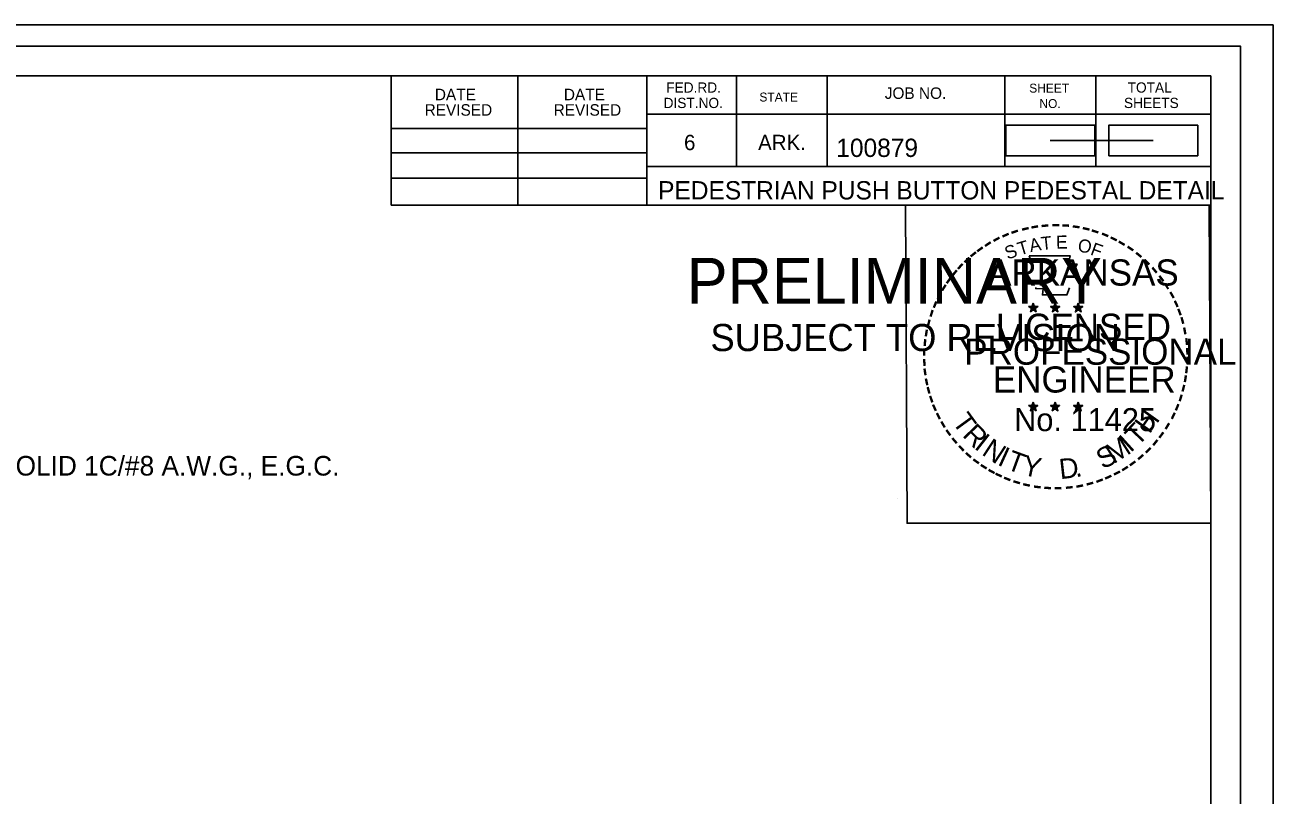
# Model space of a CAD drawing. Extents: x 1695551 to 1695718, y 544410 to 544516.
# Drawn here: x 1695670.25 to 1695717.93, y 544486.76 to 544516.2 of the extents above; entities that cross this region are included whole.
import ezdxf

# ---------------------------------------------------------------- set-up
doc = ezdxf.new("R2010")
doc.units = 0
for name, color, linetype in [('0_Plot Shape', 7, 'Continuous'), ('R_Border', 7, 'Continuous'), ('R_Border PE', 7, 'Continuous'), ('R_Border Prem', 7, 'Continuous'), ('R_Draft', 7, 'Continuous'), ('R_No Plot', 7, 'Continuous'), ('R_NoPlot', 7, 'Continuous'), ('R_Proposed Road', 7, 'Continuous')]:
    doc.layers.add(name, color=color, linetype=linetype)

msp = doc.modelspace()

# ---------------------------------------------------------------- linework, layer by layer
at = {"layer": '0_Plot Shape'}
msp.add_lwpolyline([(1695551.694, 544515.386), (1695716.694, 544515.386), (1695716.694, 544410.386), (1695551.694, 544410.386)], close=True, dxfattribs=at)
at = {"layer": 'R_Border'}
for p, q in [((1695557.469, 544514.251), (1695715.559, 544514.251)), ((1695684.239, 544509.311), (1695684.239, 544514.251)), ((1695689.079, 544509.311), (1695689.079, 544514.251)), ((1695694.009, 544514.251), (1695694.009, 544509.311)), ((1695697.429, 544514.251), (1695697.429, 544510.781)), ((1695700.899, 544514.251), (1695700.899, 544510.781)), ((1695707.689, 544514.251), (1695707.689, 544510.781)), ((1695711.159, 544514.251), (1695711.159, 544510.781)), ((1695715.559, 544411.521), (1695715.559, 544514.251)), ((1695715.559, 544512.781), (1695694.009, 544512.781)), ((1695715.559, 544512.791), (1695715.559, 544512.791)), ((1695684.239, 544512.241), (1695694.009, 544512.241)), ((1695684.239, 544511.311), (1695694.009, 544511.311)), ((1695715.559, 544510.781), (1695694.009, 544510.781)), ((1695695.489, 544510.781), (1695715.559, 544510.781)), ((1695684.239, 544510.341), (1695694.009, 544510.341)), ((1695715.559, 544509.311), (1695684.239, 544509.311))]:
    msp.add_line(p, q, dxfattribs=at)
msp.add_lwpolyline([(1695711.657, 544511.198), (1695715.06, 544511.198), (1695715.06, 544512.364), (1695711.657, 544512.364)], close=True, dxfattribs=at)
at = {"layer": 'R_Border PE'}
for p, q in [((1695708.601, 544505.438), (1695708.776, 544505.383)), ((1695708.601, 544505.438), (1695708.728, 544505.416)), ((1695708.601, 544505.438), (1695708.72, 544505.377)), ((1695708.668, 544505.234), (1695708.776, 544505.383)), ((1695708.668, 544505.234), (1695708.731, 544505.356)), ((1695708.668, 544505.234), (1695708.775, 544505.343)), ((1695708.776, 544505.565), (1695708.755, 544505.439)), ((1695708.882, 544505.234), (1695708.775, 544505.341)), ((1695708.776, 544505.383), (1695708.776, 544505.565)), ((1695708.776, 544505.565), (1695708.8, 544505.44)), ((1695708.949, 544505.438), (1695708.776, 544505.383)), ((1695708.882, 544505.234), (1695708.776, 544505.383)), ((1695708.949, 544505.438), (1695708.806, 544505.414)), ((1695708.882, 544505.234), (1695708.814, 544505.38)), ((1695708.949, 544505.438), (1695708.847, 544505.387)), ((1695709.436, 544505.438), (1695709.611, 544505.383)), ((1695709.436, 544505.438), (1695709.563, 544505.416)), ((1695709.436, 544505.438), (1695709.555, 544505.377)), ((1695709.503, 544505.234), (1695709.611, 544505.383)), ((1695709.503, 544505.234), (1695709.566, 544505.356)), ((1695709.503, 544505.234), (1695709.61, 544505.343)), ((1695709.611, 544505.565), (1695709.59, 544505.439)), ((1695709.717, 544505.234), (1695709.61, 544505.341)), ((1695709.611, 544505.383), (1695709.611, 544505.565)), ((1695709.611, 544505.565), (1695709.635, 544505.44)), ((1695709.784, 544505.438), (1695709.611, 544505.383)), ((1695709.717, 544505.234), (1695709.611, 544505.383)), ((1695709.784, 544505.438), (1695709.641, 544505.414)), ((1695709.717, 544505.234), (1695709.649, 544505.38)), ((1695709.784, 544505.438), (1695709.682, 544505.387)), ((1695710.318, 544505.432), (1695710.493, 544505.377)), ((1695710.318, 544505.432), (1695710.445, 544505.41)), ((1695710.318, 544505.432), (1695710.437, 544505.371)), ((1695710.385, 544505.228), (1695710.493, 544505.377)), ((1695710.385, 544505.228), (1695710.448, 544505.35)), ((1695710.385, 544505.228), (1695710.492, 544505.337)), ((1695710.493, 544505.559), (1695710.472, 544505.433)), ((1695710.599, 544505.228), (1695710.492, 544505.335)), ((1695710.493, 544505.377), (1695710.493, 544505.559)), ((1695710.493, 544505.559), (1695710.517, 544505.434)), ((1695710.666, 544505.432), (1695710.493, 544505.377)), ((1695710.599, 544505.228), (1695710.493, 544505.377)), ((1695710.666, 544505.432), (1695710.523, 544505.408)), ((1695710.599, 544505.228), (1695710.531, 544505.374)), ((1695710.666, 544505.432), (1695710.564, 544505.381)), ((1695708.599, 544501.652), (1695708.774, 544501.596)), ((1695708.599, 544501.652), (1695708.726, 544501.629)), ((1695708.599, 544501.652), (1695708.718, 544501.591)), ((1695708.666, 544501.448), (1695708.774, 544501.596)), ((1695708.666, 544501.448), (1695708.729, 544501.57)), ((1695708.666, 544501.448), (1695708.773, 544501.556)), ((1695708.774, 544501.779), (1695708.753, 544501.653)), ((1695708.88, 544501.448), (1695708.773, 544501.555)), ((1695708.774, 544501.596), (1695708.774, 544501.779)), ((1695708.774, 544501.779), (1695708.798, 544501.654)), ((1695708.947, 544501.652), (1695708.774, 544501.596)), ((1695708.88, 544501.448), (1695708.774, 544501.596)), ((1695708.947, 544501.652), (1695708.804, 544501.627)), ((1695708.88, 544501.448), (1695708.812, 544501.593)), ((1695708.947, 544501.652), (1695708.845, 544501.601)), ((1695709.434, 544501.652), (1695709.608, 544501.596)), ((1695709.434, 544501.652), (1695709.56, 544501.629)), ((1695709.434, 544501.652), (1695709.552, 544501.591)), ((1695709.5, 544501.448), (1695709.608, 544501.596)), ((1695709.5, 544501.448), (1695709.563, 544501.57)), ((1695709.5, 544501.448), (1695709.607, 544501.556)), ((1695709.608, 544501.779), (1695709.588, 544501.653)), ((1695709.715, 544501.448), (1695709.607, 544501.555)), ((1695709.608, 544501.596), (1695709.608, 544501.779)), ((1695709.608, 544501.779), (1695709.633, 544501.654)), ((1695709.782, 544501.652), (1695709.608, 544501.596)), ((1695709.715, 544501.448), (1695709.608, 544501.596)), ((1695709.782, 544501.652), (1695709.639, 544501.627)), ((1695709.715, 544501.448), (1695709.646, 544501.593)), ((1695709.782, 544501.652), (1695709.68, 544501.601)), ((1695710.317, 544501.647), (1695710.492, 544501.591)), ((1695710.317, 544501.647), (1695710.444, 544501.624)), ((1695710.317, 544501.647), (1695710.436, 544501.586)), ((1695710.384, 544501.443), (1695710.492, 544501.591)), ((1695710.384, 544501.443), (1695710.447, 544501.565)), ((1695710.384, 544501.443), (1695710.491, 544501.551)), ((1695710.492, 544501.774), (1695710.471, 544501.648)), ((1695710.598, 544501.443), (1695710.491, 544501.55)), ((1695710.492, 544501.591), (1695710.492, 544501.774)), ((1695710.492, 544501.774), (1695710.516, 544501.649)), ((1695710.665, 544501.647), (1695710.492, 544501.591)), ((1695710.598, 544501.443), (1695710.492, 544501.591)), ((1695710.665, 544501.647), (1695710.522, 544501.622)), ((1695710.598, 544501.443), (1695710.53, 544501.588)), ((1695710.665, 544501.647), (1695710.563, 544501.596))]:
    msp.add_line(p, q, dxfattribs=at)
for points in [[(1695708.622, 544507.377), (1695708.756, 544506.964)], [(1695710.377, 544506.916), (1695710.448, 544507.058), (1695710.106, 544507.046), (1695710.18, 544507.377), (1695708.622, 544507.377)], [(1695708.868, 544506.166), (1695708.868, 544506.122), (1695709.149, 544506.113), (1695709.122, 544505.876), (1695710.057, 544505.876), (1695710.158, 544506.144)], [(1695708.776, 544505.565), (1695708.882, 544505.234), (1695708.601, 544505.438), (1695708.949, 544505.438), (1695708.668, 544505.234), (1695708.776, 544505.565)], [(1695709.611, 544505.565), (1695709.717, 544505.234), (1695709.436, 544505.438), (1695709.784, 544505.438), (1695709.503, 544505.234), (1695709.611, 544505.565)], [(1695710.493, 544505.559), (1695710.599, 544505.228), (1695710.318, 544505.432), (1695710.666, 544505.432), (1695710.385, 544505.228), (1695710.493, 544505.559)], [(1695708.774, 544501.779), (1695708.88, 544501.448), (1695708.599, 544501.652), (1695708.947, 544501.652), (1695708.666, 544501.448), (1695708.774, 544501.779)], [(1695709.608, 544501.779), (1695709.715, 544501.448), (1695709.434, 544501.652), (1695709.782, 544501.652), (1695709.5, 544501.448), (1695709.608, 544501.779)], [(1695710.492, 544501.774), (1695710.598, 544501.443), (1695710.317, 544501.647), (1695710.665, 544501.647), (1695710.384, 544501.443), (1695710.492, 544501.774)]]:
    msp.add_lwpolyline(points, dxfattribs=at)
for centre, radius in [((1695708.775, 544505.383), 0.0861), ((1695708.775, 544505.383), 0.0723), ((1695708.775, 544505.383), 0.0579), ((1695708.775, 544505.383), 0.0495), ((1695708.775, 544505.383), 0.0374), ((1695708.775, 544505.383), 0.0248), ((1695708.775, 544505.383), 0.0148), ((1695709.61, 544505.383), 0.0861), ((1695709.61, 544505.383), 0.0723), ((1695709.61, 544505.383), 0.0579), ((1695709.61, 544505.383), 0.0495), ((1695709.61, 544505.383), 0.0374), ((1695709.61, 544505.383), 0.0248), ((1695709.61, 544505.383), 0.0148), ((1695710.492, 544505.377), 0.0861), ((1695710.492, 544505.377), 0.0723), ((1695710.492, 544505.377), 0.0579), ((1695710.492, 544505.377), 0.0495), ((1695710.492, 544505.377), 0.0374), ((1695710.492, 544505.377), 0.0248), ((1695710.492, 544505.377), 0.0148), ((1695708.773, 544501.596), 0.0861), ((1695708.773, 544501.596), 0.0723), ((1695708.773, 544501.596), 0.0579), ((1695708.773, 544501.596), 0.0495), ((1695708.773, 544501.596), 0.0374), ((1695708.773, 544501.596), 0.0248), ((1695708.773, 544501.596), 0.0148), ((1695709.608, 544501.596), 0.0861), ((1695709.608, 544501.596), 0.0723), ((1695709.608, 544501.596), 0.0579), ((1695709.608, 544501.596), 0.0495), ((1695709.608, 544501.596), 0.0374), ((1695709.608, 544501.596), 0.0248), ((1695709.608, 544501.596), 0.0148), ((1695710.491, 544501.591), 0.0861), ((1695710.491, 544501.591), 0.0723), ((1695710.491, 544501.591), 0.0579), ((1695710.491, 544501.591), 0.0495), ((1695710.491, 544501.591), 0.0374), ((1695710.491, 544501.591), 0.0248), ((1695710.491, 544501.591), 0.0148)]:
    msp.add_circle(centre, radius, dxfattribs=at)
at = {"layer": 'R_No Plot'}
for p, q in [((1695551.268, 544516.198), (1695717.935, 544516.198)), ((1695703.576, 544498.083), (1695703.576, 544498.083))]:
    msp.add_line(p, q, dxfattribs=at)
for points in [[(1695551.265, 544516.198), (1695717.935, 544516.198), (1695717.935, 544409.529), (1695551.265, 544409.529)], [(1695703.894, 544509.311), (1695715.498, 544509.311), (1695715.559, 544497.145), (1695703.955, 544497.145)]]:
    msp.add_lwpolyline(points, close=True, dxfattribs=at)
at = {"layer": 'R_NoPlot'}
msp.add_line((1695709.424, 544511.781), (1695713.359, 544511.781), dxfattribs=at)
at = {"layer": 'R_Proposed Road'}
msp.add_lwpolyline([(1695707.722, 544511.198), (1695711.125, 544511.198), (1695711.125, 544512.364), (1695707.722, 544512.364)], close=True, dxfattribs=at)

# ---------------------------------------------------------------- texts
at = {"layer": 'R_Border'}
for s, height, p in [('FED.RD.', 0.391, (1695694.749, 544513.611)), ('JOB NO.', 0.4396, (1695703.099, 544513.371)), ('SHEET', 0.342, (1695708.619, 544513.611)), ('TOTAL', 0.391, (1695712.379, 544513.611)), ('DATE', 0.4396, (1695685.908, 544513.319)), ('DATE', 0.4396, (1695690.838, 544513.319)), ('DIST.NO.', 0.391, (1695694.649, 544513.021)), ('STATE', 0.342, (1695698.309, 544513.271)), ('NO.', 0.342, (1695709.009, 544513.021)), ('SHEETS', 0.391, (1695712.239, 544513.021)), ('REVISED', 0.4396, (1695685.518, 544512.729)), ('REVISED', 0.4396, (1695690.448, 544512.729)), ('6', 0.586, (1695695.429, 544511.411)), ('ARK.', 0.5861, (1695698.259, 544511.411)), ('100879', 0.7, (1695701.247, 544511.151)), ('PEDESTRIAN PUSH BUTTON PEDESTAL DETAIL', 0.7, (1695694.44, 544509.526))]:
    msp.add_text(s, height=height, dxfattribs=at).set_placement(p)
at = {"layer": 'R_Border PE'}
for s, height, rotation, p in [('-', 0.8, 10.2193, (1695708.71, 544508.142)), ('-', 0.8, 5.8968, (1695709.074, 544508.197)), ('-', 0.8, 0.1862, (1695709.46, 544508.233)), ('-', 0.8, 357.743, (1695709.822, 544508.227)), ('-', 0.8, 352.1617, (1695710.194, 544508.199)), ('-', 0.8, 28.7918, (1695707.362, 544507.648)), ('-', 0.8, 24.3072, (1695707.679, 544507.806)), ('-', 0.8, 19.1761, (1695707.996, 544507.941)), ('-', 0.8, 13.6302, (1695708.371, 544508.061)), ('T', 0.5, 6.0228, (1695709.094, 544507.59)), ('E', 0.5, 0.8323, (1695709.646, 544507.645)), ('-', 0.8, 347.2049, (1695710.553, 544508.142)), ('-', 0.8, 342.3362, (1695710.871, 544508.064)), ('-', 0.8, 337.8551, (1695711.238, 544507.953)), ('-', 0.8, 334.1211, (1695711.554, 544507.817)), ('-', 0.8, 36.2317, (1695706.775, 544507.265)), ('-', 0.8, 34.0636, (1695707.064, 544507.463)), ('S', 0.5, 21.594, (1695707.799, 544507.216)), ('T', 0.5, 16.4036, (1695708.256, 544507.382)), ('A', 0.5, 11.2132, (1695708.669, 544507.507)), ('O', 0.5, 350.4515, (1695710.448, 544507.54)), ('F', 0.5, 340.0707, (1695710.925, 544507.426)), ('-', 0.8, 329.6409, (1695711.843, 544507.676)), ('-', 0.8, 325.8627, (1695712.165, 544507.495)), ('-', 0.8, 42.9622, (1695706.32, 544506.868)), ('-', 0.8, 38.9507, (1695706.537, 544507.076)), ('-', 0.8, 320.5297, (1695712.47, 544507.282)), ('-', 0.8, 315.5786, (1695712.769, 544507.038)), ('-', 0.8, 50.6142, (1695705.895, 544506.386)), ('-', 0.8, 48.4231, (1695706.096, 544506.629)), ('-', 0.8, 309.8797, (1695713.054, 544506.763)), ('-', 0.8, 306.6522, (1695713.316, 544506.462)), ('-', 0.8, 58.0706, (1695705.526, 544505.839)), ('-', 0.8, 54.2325, (1695705.688, 544506.102)), ('-', 0.7, 303.6753, (1695713.559, 544506.178)), ('-', 0.8, 62.8713, (1695705.369, 544505.532)), ('-', 0.8, 299.6684, (1695713.719, 544505.875)), ('-', 0.8, 72.3945, (1695705.13, 544504.911)), ('-', 0.8, 67.7743, (1695705.24, 544505.226)), ('-', 0.8, 294.6628, (1695713.881, 544505.569)), ('-', 0.8, 290.5728, (1695714.009, 544505.28)), ('-', 0.8, 75.461, (1695705.032, 544504.554)), ('-', 0.8, 285.1233, (1695714.126, 544504.99)), ('-', 0.8, 81.2013, (1695704.966, 544504.198)), ('-', 0.8, 280.5493, (1695714.226, 544504.619)), ('-', 0.8, 89.0622, (1695704.915, 544503.502)), ('-', 0.8, 85.1863, (1695704.928, 544503.852)), ('-', 0.8, 276.5962, (1695714.307, 544504.235)), ('-', 0.8, 274.3301, (1695714.337, 544503.874)), ('-', 0.8, 94.1959, (1695704.933, 544503.139)), ('-', 0.8, 269.9407, (1695714.354, 544503.558)), ('-', 0.8, 98.9479, (1695704.969, 544502.806)), ('-', 0.8, 263.5172, (1695714.345, 544503.225)), ('-', 0.8, 101.7149, (1695705.036, 544502.439)), ('-', 0.8, 105.4578, (1695705.117, 544502.142)), ('-', 0.8, 255.7626, (1695714.254, 544502.559)), ('-', 0.8, 260.9953, (1695714.309, 544502.898)), ('-', 0.8, 109.0874, (1695705.225, 544501.826)), ('-', 0.8, 252.8681, (1695714.164, 544502.199)), ('-', 0.8, 114.0643, (1695705.352, 544501.528)), ('T', 0.77, 306.0406, (1695705.653, 544501.015)), ('H', 0.77, 54.6088, (1695713.214, 544500.533)), ('-', 0.8, 244.6197, (1695713.921, 544501.548)), ('-', 0.8, 247.8887, (1695714.052, 544501.863)), ('-', 0.8, 115.7289, (1695705.504, 544501.219)), ('-', 0.8, 120.4471, (1695705.683, 544500.926)), ('R', 0.77, 314.005, (1695706.035, 544500.492)), ('T', 0.77, 46.6444, (1695712.769, 544500.062)), ('-', 0.8, 239.0712, (1695713.724, 544501.172)), ('-', 0.8, 125.8934, (1695705.884, 544500.646)), ('I', 0.77, 321.9694, (1695706.485, 544500.026)), ('M', 0.77, 32.6563, (1695711.846, 544499.399)), ('I', 0.77, 42.1136, (1695712.488, 544499.823)), ('-', 0.8, 233.8452, (1695713.523, 544500.846)), ('-', 0.8, 130.7181, (1695706.115, 544500.37)), ('-', 0.8, 134.2238, (1695706.374, 544500.097)), ('N', 0.77, 326.5002, (1695706.768, 544499.79)), ('I', 0.77, 335.3603, (1695707.373, 544499.397)), ('S', 0.77, 26.9312, (1695711.426, 544499.196)), ('-', 0.8, 225.7653, (1695713.069, 544500.281)), ('-', 0.8, 231.2538, (1695713.308, 544500.563)), ('-', 0.8, 138.9338, (1695706.636, 544499.865)), ('-', 0.8, 144.6463, (1695706.914, 544499.662)), ('T', 0.77, 339.8912, (1695707.703, 544499.233)), ('Y', 0.77, 347.8556, (1695708.312, 544499.01)), ('D', 0.77, 6.3969, (1695709.804, 544498.831)), ('-', 0.8, 215.7363, (1695712.533, 544499.79)), ('-', 0.8, 221.0851, (1695712.808, 544500.026)), ('-', 0.8, 148.0898, (1695707.195, 544499.477)), ('-', 0.8, 151.5704, (1695707.484, 544499.314)), ('-', 0.8, 154.6002, (1695707.745, 544499.191)), ('.', 0.77, 13.7642, (1695710.4, 544498.895)), ('-', 0.8, 204.2516, (1695711.675, 544499.264)), ('-', 0.8, 207.3568, (1695711.987, 544499.424)), ('-', 0.8, 212.2491, (1695712.266, 544499.597)), ('-', 0.8, 158.5612, (1695708.057, 544499.064)), ('-', 0.8, 162.7983, (1695708.401, 544498.957)), ('-', 0.8, 167.5555, (1695708.758, 544498.875)), ('-', 0.8, 173.1155, (1695709.144, 544498.82)), ('-', 0.8, 176.5183, (1695709.518, 544498.794)), ('-', 0.8, 181.5918, (1695709.89, 544498.803)), ('-', 0.8, 185.8167, (1695710.295, 544498.841)), ('-', 0.8, 191.2858, (1695710.663, 544498.907)), ('-', 0.8, 195.4743, (1695711.027, 544499.007)), ('-', 0.8, 200.7184, (1695711.366, 544499.128))]:
    msp.add_text(s, height=height, rotation=rotation, dxfattribs=at).set_placement(p)
for s, height, p in [('ARKANSAS', 1, (1695707.048, 544506.233)), ('DWB', 0.005, (1695708.769, 544505.38)), ('DWB', 0.005, (1695709.604, 544505.38)), ('DWB', 0.005, (1695710.486, 544505.375)), ('LICENSED', 1, (1695707.347, 544504.159)), ('PROFESSIONAL', 1, (1695706.135, 544503.207)), ('ENGINEER', 1, (1695707.229, 544502.144)), ('No. 11425', 0.8785, (1695708.042, 544500.669)), ('DWB', 0.005, (1695708.767, 544501.594)), ('DWB', 0.005, (1695709.602, 544501.594)), ('DWB', 0.005, (1695710.485, 544501.589))]:
    msp.add_text(s, height=height, dxfattribs=at).set_placement(p)
at = {"layer": 'R_Border Prem'}
for s, height, p in [('PRELIMINARY', 1.75, (1695695.534, 544505.542)), ('DWB', 0.005, (1695695.908, 544506.467)), ('SUBJECT TO REVISION', 1.03756, (1695696.439, 544503.728))]:
    msp.add_text(s, height=height, dxfattribs=at).set_placement(p)
at = {"layer": 'R_Draft'}
msp.add_text(' 1/2" NMC WITH A SOLID 1C/#8 A.W.G., E.G.C.', height=0.75, dxfattribs=at).set_placement((1695660.562, 544498.97))

doc.saveas('drawing.dxf')
